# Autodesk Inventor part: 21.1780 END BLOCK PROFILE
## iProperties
Company: MiniTec Framing Systems, LLC
Created: 2007-05
Part Number: 21.1780 END BLOCK PROFILE
Material: Aluminum-6061
Document SubType Name: Modeling
Designer: Andy Moles
Density: 2.71 g/cm^3
Author: Andy Moles
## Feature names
1. Extrusion1
2. Extrusion2
3. Hole1
